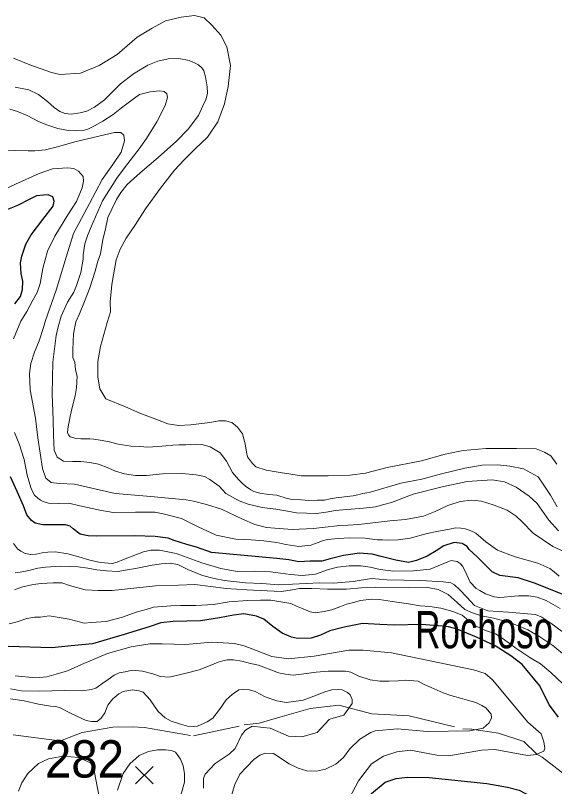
# Model space of a CAD drawing. Extents: x 474.5 to 500, y 7345.7 to 7373.4.
# Drawn here: x 485.568 to 486.724, y 7367.259 to 7368.914 of the extents above; entities that cross this region are included whole.
import ezdxf
from ezdxf.enums import TextEntityAlignment as Align

# ---------------------------------------------------------------- set-up
doc = ezdxf.new("R2010")
doc.units = 0
doc.header["$LTSCALE"] = 0.032
doc.linetypes.add('SHORT_DASHED', pattern=[2.7, 1.5, -1.2])
for name, color, linetype, lineweight in [('1', 7, 'Continuous', 25), ('16', 7, 'SHORT_DASHED', 13), ('2', 7, 'Continuous', 13), ('21', 7, 'Continuous', 25)]:
    doc.layers.add(name, color=color, linetype=linetype, lineweight=lineweight)
doc.layers.add('61', color=7, linetype='Continuous')

msp = doc.modelspace()

# ---------------------------------------------------------------- linework, layer by layer
at = {"layer": '1'}
for points in [[(485.5666, 7368.2952), (485.5789, 7368.3109), (485.583, 7368.3258), (485.5836, 7368.3436), (485.5802, 7368.3599), (485.5789, 7368.3831), (485.5816, 7368.3974), (485.5905, 7368.4226), (485.6014, 7368.4431), (485.6266, 7368.4758), (485.6491, 7368.5044), (485.6511, 7368.5153), (485.6484, 7368.5242), (485.6382, 7368.5289), (485.6279, 7368.5283), (485.6129, 7368.5269), (485.5973, 7368.5187), (485.5721, 7368.5058), (485.5325, 7368.4901)], [(486.225, 7367.7431), (486.1997, 7367.7431), (486.1752, 7367.7418), (486.1541, 7367.7459), (486.1282, 7367.7486), (485.9885, 7367.7615), (485.9564, 7367.7731), (485.9353, 7367.7786), (485.908, 7367.7874), (485.8951, 7367.7922), (485.8672, 7367.7956), (485.8242, 7367.797), (485.7411, 7367.7963), (485.724, 7367.797), (485.707, 7367.8011), (485.692, 7367.812), (485.6852, 7367.8181), (485.675, 7367.8208), (485.6634, 7367.8208), (485.6457, 7367.8208), (485.6266, 7367.8208), (485.6102, 7367.8242), (485.6021, 7367.8299), (485.5925, 7367.8426), (485.585, 7367.8617), (485.5714, 7367.8924), (485.5571, 7367.9237)], [(486.7402, 7367.6723), (486.6809, 7367.6954), (486.6455, 7367.707), (486.6066, 7367.7125), (486.5902, 7367.72), (486.5575, 7367.752), (486.5405, 7367.7677), (486.5364, 7367.7745), (486.5255, 7367.7806), (486.5085, 7367.7827), (486.486, 7367.7759), (486.4696, 7367.765), (486.4505, 7367.754), (486.4274, 7367.7445), (486.4103, 7367.7404), (486.3831, 7367.7452), (486.3517, 7367.7527), (486.3326, 7367.7581), (486.3047, 7367.7602), (486.2911, 7367.7581), (486.2713, 7367.7554), (486.2427, 7367.7479), (486.225, 7367.7431)], [(486.712, 7367.4346), (486.6924, 7367.4752), (486.6541, 7367.5213), (486.6298, 7367.5401), (486.5962, 7367.5612), (486.5563, 7367.58), (486.5148, 7367.5972), (486.496, 7367.6019), (486.4835, 7367.6035), (486.4374, 7367.6074), (486.3802, 7367.6058), (486.3489, 7367.6074), (486.3122, 7367.609), (486.273, 7367.6011), (486.2417, 7367.5933), (486.2222, 7367.5839), (486.2018, 7367.5777), (486.1729, 7367.5769), (486.1596, 7367.58), (486.14, 7367.5886), (486.1197, 7367.6027), (486.1001, 7367.6184), (486.0845, 7367.6246), (486.0578, 7367.6301), (486.0352, 7367.627), (486.0054, 7367.6215), (485.9647, 7367.6152), (485.906, 7367.6137), (485.8794, 7367.6105), (485.8544, 7367.6019), (485.8012, 7367.5855), (485.7331, 7367.5659), (485.6877, 7367.5612), (485.6463, 7367.5573), (485.5524, 7367.5597)], [(486.7321, 7367.4081), (486.712, 7367.4346)], [(486.2289, 7367.1554), (486.2404, 7367.1554), (486.2526, 7367.1591), (486.2725, 7367.1732), (486.3093, 7367.2226), (486.3313, 7367.2447), (486.3602, 7367.2686), (486.3841, 7367.2766), (486.4087, 7367.2798), (486.455, 7367.2791), (486.5783, 7367.2659), (486.6226, 7367.2584), (486.6476, 7367.2517), (486.6709, 7367.2393), (486.6958, 7367.2218), (486.7433, 7367.1823)]]:
    msp.add_lwpolyline(points, dxfattribs=at)
at = {"layer": '16'}
for points in [[(486.7287, 7367.9511), (486.7154, 7367.9692), (486.7022, 7367.9764), (486.6841, 7367.9836), (486.642, 7367.9848), (486.577, 7367.9848), (486.5276, 7367.98), (486.4891, 7367.9728), (486.4385, 7367.9584), (486.3651, 7367.9439), (486.3182, 7367.9319), (486.2845, 7367.9271), (486.2387, 7367.9259), (486.1809, 7367.9259), (486.1352, 7367.9331), (486.1051, 7367.9379), (486.0834, 7367.9451), (486.0762, 7367.9523), (486.0654, 7367.9668), (486.063, 7367.9764), (486.0606, 7367.9945), (486.0545, 7368.0161), (486.0437, 7368.0306), (486.0317, 7368.0402), (486.0184, 7368.0438), (486.004, 7368.0438), (485.9847, 7368.0402), (485.9438, 7368.0354), (485.9173, 7368.0342), (485.8944, 7368.0378), (485.8692, 7368.0474), (485.8343, 7368.0607), (485.8042, 7368.0739), (485.7616, 7368.091), (485.7488, 7368.1128), (485.7449, 7368.1373), (485.7449, 7368.1709), (485.75, 7368.2032), (485.7643, 7368.2549), (485.772, 7368.2781), (485.7707, 7368.3001), (485.7733, 7368.3207), (485.7746, 7368.3362), (485.7785, 7368.3569), (485.7836, 7368.3892), (485.7927, 7368.4124), (485.8056, 7368.4357), (485.825, 7368.4654), (485.8469, 7368.499), (485.8792, 7368.5429), (485.9089, 7368.5816), (485.9296, 7368.6036), (485.9541, 7368.6281), (485.98, 7368.6527), (486.0019, 7368.685), (486.0161, 7368.7237), (486.0239, 7368.7612), (486.029, 7368.8064), (486.0213, 7368.8464), (486.0084, 7368.871), (485.989, 7368.8929), (485.9722, 7368.9084), (485.9515, 7368.9136), (485.9231, 7368.9097), (485.8895, 7368.902), (485.8611, 7368.8865)], [(485.8611, 7368.8865), (485.8288, 7368.8671), (485.7862, 7368.8296), (485.7475, 7368.8064), (485.7074, 7368.7896), (485.6635, 7368.787), (485.6454, 7368.7909), (485.5989, 7368.8077), (485.5641, 7368.8219)], [(485.5634, 7367.3703), (485.6649, 7367.3573), (485.7113, 7367.3752), (485.7769, 7367.3869), (485.8183, 7367.3874), (485.8446, 7367.3864), (485.95, 7367.3681), (486.0583, 7367.3915), (486.0907, 7367.3952), (486.1348, 7367.4084), (486.2, 7367.4267), (486.261, 7367.4337), (486.3323, 7367.4156), (486.4123, 7367.4113), (486.5267, 7367.3832), (486.5461, 7367.3824), (486.5454, 7367.3825), (486.6034, 7367.374), (486.6575, 7367.3561), (486.6858, 7367.3286), (486.6974, 7367.3228), (486.7471, 7367.2839)]]:
    msp.add_lwpolyline(points, dxfattribs=at)
at = {"layer": '2'}
for points in [[(485.5674, 7368.7597), (485.5967, 7368.7537), (485.6172, 7368.7441), (485.6365, 7368.7286), (485.6507, 7368.7163), (485.663, 7368.7073), (485.6749, 7368.703), (485.6872, 7368.702), (485.7068, 7368.7046), (485.721, 7368.7083), (485.7372, 7368.7166), (485.7591, 7368.7325), (485.7931, 7368.7668), (485.8209, 7368.788), (485.8521, 7368.8072), (485.8733, 7368.8158), (485.8951, 7368.8208), (485.9181, 7368.821), (485.9405, 7368.8167), (485.953, 7368.8111), (485.9607, 7368.8077), (485.9673, 7368.8011), (485.9716, 7368.7945), (485.9756, 7368.7816), (485.9792, 7368.7607), (485.9794, 7368.7468), (485.9771, 7368.7348), (485.9698, 7368.7199), (485.9602, 7368.6987), (485.938, 7368.6696), (485.9135, 7368.644), (485.8739, 7368.6089), (485.8355, 7368.5761), (485.8078, 7368.5506), (485.7936, 7368.5337), (485.7843, 7368.5184), (485.7747, 7368.4982), (485.7663, 7368.4803), (485.7603, 7368.4521), (485.7553, 7368.4326), (485.7502, 7368.4024), (485.7449, 7368.3865), (485.7389, 7368.365), (485.7271, 7368.3295), (485.7159, 7368.2997), (485.7051, 7368.2732), (485.6975, 7368.2566), (485.6925, 7368.2308), (485.6907, 7368.1965), (485.6913, 7368.1799), (485.695, 7368.17), (485.6966, 7368.1531), (485.7003, 7368.1395), (485.699, 7368.115), (485.696, 7368.0978), (485.6882, 7368.0667), (485.6856, 7368.0534), (485.6836, 7368.0454), (485.6809, 7368.0319), (485.6794, 7368.0186), (485.6814, 7368.0137), (485.685, 7368.0097), (485.6907, 7368.008), (485.6973, 7368.0061), (485.7082, 7368.0051), (485.7274, 7368.0054), (485.7357, 7368.0047), (485.7496, 7368.0027), (485.7698, 7367.9988), (485.7884, 7367.9941), (485.816, 7367.9895), (485.8346, 7367.9888), (485.8521, 7367.9878), (485.873, 7367.9891), (485.8902, 7367.9905), (485.9055, 7367.9918), (485.919, 7367.9924), (485.9333, 7367.9928), (485.9439, 7367.9934)], [(486.1479, 7367.8511), (486.1259, 7367.8542), (486.0972, 7367.8581), (486.0672, 7367.8652), (486.0474, 7367.8722), (486.0188, 7367.8881), (486.0046, 7367.9035), (485.9844, 7367.9181), (485.9733, 7367.9242), (485.9553, 7367.9282), (485.9244, 7367.9313), (485.8834, 7367.93), (485.849, 7367.9269), (485.8252, 7367.9265), (485.8019, 7367.9304), (485.7825, 7367.9357), (485.7684, 7367.9423), (485.7463, 7367.9507), (485.7274, 7367.9547), (485.708, 7367.9564), (485.6903, 7367.9564), (485.6709, 7367.9573), (485.6577, 7367.9661), (485.6513, 7367.9809), (485.6498, 7368.0124), (485.6485, 7368.0459), (485.6467, 7368.1015), (485.648, 7368.1698), (485.6551, 7368.2267), (485.6595, 7368.2456), (485.6657, 7368.2685), (485.6798, 7368.2985), (485.693, 7368.3201), (485.6987, 7368.3342), (485.708, 7368.362), (485.7133, 7368.3906), (485.7133, 7368.4003), (485.7168, 7368.4233), (485.7234, 7368.4427), (485.7344, 7368.4704), (485.7547, 7368.5158), (485.7856, 7368.5643), (485.8036, 7368.5895), (485.8332, 7368.6274), (485.8486, 7368.6499), (485.8711, 7368.6851), (485.8892, 7368.7204), (485.894, 7368.7376), (485.8927, 7368.7455), (485.8865, 7368.7504), (485.8764, 7368.7517), (485.857, 7368.7499), (485.8336, 7368.7442), (485.8151, 7368.7305), (485.7953, 7368.7155), (485.7776, 7368.701), (485.7556, 7368.6869), (485.7375, 7368.6767), (485.7234, 7368.6693), (485.7128, 7368.6666), (485.6992, 7368.6657), (485.6815, 7368.667), (485.6586, 7368.671), (485.633, 7368.6794), (485.6172, 7368.6864), (485.5934, 7368.6992), (485.5722, 7368.7072), (485.5559, 7368.7125)], [(485.8018, 7368.6447), (485.8004, 7368.6564), (485.7937, 7368.6622), (485.7802, 7368.6622), (485.6981, 7368.6429), (485.6555, 7368.6308), (485.6326, 7368.6254), (485.6093, 7368.6232), (485.5953, 7368.6232), (485.5424, 7368.6245)], [(486.7842, 7367.7449), (486.72, 7367.7741), (486.6778, 7367.8033), (486.6545, 7367.8275), (486.6415, 7367.8396), (486.6222, 7367.8522), (486.5939, 7367.8629), (486.567, 7367.8715), (486.5463, 7367.8737), (486.5212, 7367.8706), (486.4947, 7367.8621), (486.4678, 7367.8495), (486.4426, 7367.8396), (486.4041, 7367.832), (486.3704, 7367.8297), (486.3044, 7367.8217), (486.2573, 7367.819), (486.207, 7367.8127), (486.1613, 7367.8109), (486.133, 7367.8127), (486.1065, 7367.8154), (486.0814, 7367.8217), (486.0545, 7367.8333), (486.01, 7367.8544), (485.9773, 7367.8643), (485.9499, 7367.8715), (485.9342, 7367.8746), (485.8583, 7367.8818), (485.7816, 7367.8881), (485.7286, 7367.9002), (485.6945, 7367.9083), (485.6622, 7367.9092), (485.6492, 7367.911), (485.6443, 7367.9119), (485.633, 7367.9208), (485.6259, 7367.9419), (485.616, 7368.0075), (485.6111, 7368.0496), (485.5998, 7368.1102), (485.598, 7368.1457), (485.6012, 7368.1668), (485.6088, 7368.191), (485.6187, 7368.2157), (485.6281, 7368.244), (485.6321, 7368.2592), (485.655, 7368.3243), (485.6766, 7368.3948), (485.6927, 7368.4459), (485.7264, 7368.5101), (485.7542, 7368.5613), (485.7767, 7368.5936), (485.7946, 7368.6205), (485.8018, 7368.6447)], [(485.5636, 7368.22), (485.5795, 7368.2577), (485.5922, 7368.2788), (485.6052, 7368.3029), (485.6142, 7368.3193), (485.6213, 7368.3383), (485.627, 7368.3705), (485.6369, 7368.408), (485.6522, 7368.4404), (485.6801, 7368.4862), (485.6991, 7368.5141), (485.7108, 7368.5439), (485.7142, 7368.5583), (485.7135, 7368.568), (485.7035, 7368.5797), (485.6928, 7368.5854), (485.6797, 7368.5867), (485.6476, 7368.5847), (485.6189, 7368.5744), (485.5684, 7368.5519), (485.5422, 7368.5392)], [(486.1475, 7367.7785), (486.1285, 7367.7829), (486.1007, 7367.7862), (486.0736, 7367.7886), (486.0404, 7367.7899), (485.9983, 7367.7986), (485.9595, 7367.8163), (485.9237, 7367.8347), (485.8843, 7367.8448), (485.8668, 7367.8481), (485.825, 7367.8477), (485.7775, 7367.8471), (485.7491, 7367.8521), (485.7059, 7367.8618), (485.6825, 7367.8671), (485.6598, 7367.8665), (485.6387, 7367.8675), (485.6276, 7367.8708), (485.6216, 7367.8738), (485.6159, 7367.8782), (485.6086, 7367.8845), (485.6049, 7367.8912), (485.6012, 7367.9013), (485.5929, 7367.9274), (485.5865, 7367.9612), (485.5758, 7367.9946), (485.5658, 7368.0187)], [(485.9439, 7367.9934), (485.9541, 7367.9938), (485.9675, 7367.9931), (485.9854, 7367.9882), (485.9927, 7367.9839), (486.0066, 7367.9756), (486.0205, 7367.9574), (486.0331, 7367.9328), (486.0459, 7367.9179), (486.0545, 7367.9093), (486.0614, 7367.9036), (486.0727, 7367.8957), (486.079, 7367.8927), (486.0919, 7367.8891), (486.1111, 7367.8861), (486.1283, 7367.8844), (486.1508, 7367.8775), (486.1615, 7367.8755), (486.1814, 7367.8745), (486.1966, 7367.8732), (486.2155, 7367.8735), (486.2307, 7367.8738), (486.2426, 7367.8765), (486.2552, 7367.8791), (486.2734, 7367.8808), (486.2923, 7367.8828), (486.3019, 7367.8851), (486.3119, 7367.8881), (486.3261, 7367.8904), (486.3942, 7367.9099), (486.4392, 7367.9186), (486.4814, 7367.9302), (486.5311, 7367.9424), (486.5688, 7367.9487), (486.602, 7367.9494), (486.6278, 7367.9464), (486.6568, 7367.9408), (486.6882, 7367.9239), (486.6995, 7367.908), (486.7151, 7367.8848), (486.7292, 7367.8593)], [(486.732, 7367.8083), (486.7117, 7367.8312), (486.6862, 7367.8665), (486.669, 7367.8824), (486.6416, 7367.9018), (486.6161, 7367.9132), (486.5901, 7367.9172), (486.5363, 7367.9137), (486.4825, 7367.9026), (486.4204, 7367.8863), (486.3741, 7367.8691), (486.3578, 7367.8643), (486.3401, 7367.8594), (486.3141, 7367.8564), (486.2696, 7367.8533), (486.2542, 7367.8515), (486.2343, 7367.848), (486.2136, 7367.8453), (486.192, 7367.8462), (486.1708, 7367.8467), (486.1479, 7367.8511)], [(486.7333, 7367.7107), (486.7232, 7367.7198), (486.7139, 7367.7271), (486.6875, 7367.7385), (486.639, 7367.7519), (486.6011, 7367.7665), (486.5763, 7367.7846), (486.5549, 7367.8027), (486.5429, 7367.8087), (486.5319, 7367.8124), (486.5225, 7367.8137), (486.5118, 7367.8141), (486.4984, 7367.8117), (486.4713, 7367.8067), (486.4506, 7367.802), (486.4143, 7367.792), (486.3886, 7367.7886), (486.3672, 7367.7879), (486.3548, 7367.7886), (486.3431, 7367.7889), (486.3174, 7367.7926), (486.2848, 7367.7933), (486.2601, 7367.7916), (486.2366, 7367.7893), (486.2263, 7367.7862), (486.2169, 7367.7829), (486.2012, 7367.7772), (486.1753, 7367.7745), (486.1475, 7367.7785)], [(486.0434, 7367.7206), (486.0082, 7367.727), (485.9675, 7367.7395), (485.9122, 7367.7592), (485.877, 7367.7665), (485.8582, 7367.7665), (485.8423, 7367.7626), (485.8183, 7367.7536), (485.7994, 7367.7463), (485.7861, 7367.7408), (485.775, 7367.7378), (485.7501, 7367.7399), (485.7278, 7367.7451), (485.7038, 7367.7523), (485.6802, 7367.7588), (485.6536, 7367.7626), (485.6377, 7367.7622), (485.6253, 7367.7605), (485.6124, 7367.7579), (485.6013, 7367.7571), (485.5888, 7367.7596), (485.5794, 7367.7644), (485.5725, 7367.7695), (485.564, 7367.7806)], [(486.736, 7367.6413), (486.7056, 7367.6589), (486.6867, 7367.6657), (486.6687, 7367.6683), (486.6464, 7367.6687), (486.6292, 7367.6674), (486.6155, 7367.6657), (486.6056, 7367.6653), (486.5945, 7367.6666), (486.576, 7367.673), (486.5636, 7367.6799), (486.5559, 7367.6842), (486.5426, 7367.6979), (486.5353, 7367.7137), (486.5267, 7367.7318), (486.5211, 7367.7378), (486.5147, 7367.7421), (486.5019, 7367.7442), (486.4864, 7367.7382), (486.4744, 7367.7326), (486.4568, 7367.7258), (486.4212, 7367.7219), (486.3783, 7367.7215), (486.3496, 7367.7253), (486.3282, 7367.73), (486.3084, 7367.7326), (486.2836, 7367.7326), (486.2587, 7367.73), (486.239, 7367.7249), (486.2111, 7367.715), (486.1824, 7367.7125), (486.1579, 7367.7146), (486.1146, 7367.7198), (486.0799, 7367.7215), (486.0434, 7367.7206)], [(485.7234, 7367.7282), (485.7022, 7367.7309), (485.6654, 7367.7322), (485.6327, 7367.7302), (485.6157, 7367.7282), (485.5966, 7367.7227), (485.5782, 7367.7193), (485.5673, 7367.7179)], [(486.7402, 7367.5918), (486.7156, 7367.6102), (486.6966, 7367.6225), (486.6829, 7367.6286), (486.657, 7367.6307), (486.625, 7367.6334), (486.5807, 7367.6361), (486.5521, 7367.6477), (486.5357, 7367.6655), (486.5201, 7367.6825), (486.5091, 7367.692), (486.501, 7367.6961), (486.4846, 7367.6988), (486.4369, 7367.7016), (486.364, 7367.7029), (486.3313, 7367.7057), (486.2917, 7367.6995), (486.2495, 7367.6954), (486.2202, 7367.6961), (486.1329, 7367.692), (486.0961, 7367.6948), (486.0614, 7367.6968), (486.0164, 7367.7016), (485.9939, 7367.7057), (485.9687, 7367.7125), (485.9374, 7367.7247), (485.9162, 7367.7356), (485.8999, 7367.7384), (485.8808, 7367.737), (485.861, 7367.7343), (485.8256, 7367.7275), (485.8072, 7367.7241), (485.7881, 7367.7207), (485.7629, 7367.722), (485.7424, 7367.7241), (485.7234, 7367.7282)], [(486.749, 7367.538), (486.7197, 7367.5619), (486.6918, 7367.5803), (486.6666, 7367.5959), (486.6284, 7367.6116), (486.593, 7367.6205), (486.5671, 7367.6259), (486.548, 7367.6321), (486.531, 7367.6396), (486.5146, 7367.6545), (486.4955, 7367.6716), (486.4744, 7367.6818), (486.4519, 7367.6866), (486.4124, 7367.6859), (486.3388, 7367.6873), (486.3095, 7367.6859), (486.2774, 7367.6832), (486.2372, 7367.6832), (486.2031, 7367.6845), (486.1766, 7367.6845), (486.1616, 7367.6811), (486.1377, 7367.6777), (486.1077, 7367.6791), (486.0641, 7367.6811), (486.0198, 7367.6845), (485.9523, 7367.6927), (485.9176, 7367.6913), (485.8685, 7367.69), (485.8283, 7367.6859), (485.7956, 7367.6818), (485.7751, 7367.6798), (485.7452, 7367.6798), (485.7172, 7367.6811), (485.6838, 7367.6907), (485.6675, 7367.6961), (485.6491, 7367.6961), (485.6232, 7367.6948), (485.6061, 7367.6927), (485.5809, 7367.6873), (485.5659, 7367.6811)], [(486.7417, 7367.4799), (486.7159, 7367.5041), (486.6932, 7367.5229), (486.6705, 7367.5362), (486.6408, 7367.5565), (486.6134, 7367.5761), (486.597, 7367.5871), (486.5759, 7367.5941), (486.5539, 7367.6043), (486.5391, 7367.616), (486.5258, 7367.627), (486.5054, 7367.6348), (486.4796, 7367.6418), (486.4561, 7367.6457), (486.4358, 7367.6473), (486.4107, 7367.6512), (486.3755, 7367.6567), (486.3474, 7367.6606), (486.3317, 7367.6614), (486.3067, 7367.6583), (486.2957, 7367.6551), (486.2777, 7367.6504), (486.2636, 7367.645), (486.2464, 7367.6387), (486.23, 7367.6348), (486.2104, 7367.6324), (486.1995, 7367.634), (486.1815, 7367.6418), (486.1705, 7367.6465), (486.158, 7367.652), (486.1158, 7367.6591), (486.0931, 7367.6591), (486.0657, 7367.6583), (486.0258, 7367.6559), (485.9929, 7367.6497), (485.9546, 7367.6481), (485.9217, 7367.6481), (485.9013, 7367.6473), (485.8638, 7367.6442), (485.8481, 7367.6395), (485.827, 7367.6332), (485.7973, 7367.6231), (485.7628, 7367.6137), (485.73, 7367.6113), (485.7151, 7367.6098), (485.683, 7367.6184), (485.6658, 7367.6215), (485.64, 7367.6254), (485.622, 7367.6231), (485.6087, 7367.6231), (485.5923, 7367.6199), (485.5719, 7367.6129), (485.5547, 7367.6082)], [(486.2756, 7367.2185), (486.3033, 7367.2716), (486.3316, 7367.3079), (486.3567, 7367.3243), (486.3859, 7367.3341), (486.4146, 7367.3372), (486.4713, 7367.3269), (486.4966, 7367.3253), (486.5678, 7367.3373), (486.5955, 7367.3389), (486.6659, 7367.3261), (486.6851, 7367.3283), (486.6858, 7367.3286), (486.701, 7367.3357), (486.7029, 7367.3419), (486.7006, 7367.3555), (486.6947, 7367.3728), (486.6665, 7367.3979), (486.5907, 7367.4885), (486.5751, 7367.5018), (486.55, 7367.5099), (486.3739, 7367.5465), (486.3134, 7367.5522), (486.2826, 7367.5522), (486.2082, 7367.5392), (486.1533, 7367.5332), (486.1179, 7367.5384), (486.0584, 7367.5615), (486.0373, 7367.566), (485.9889, 7367.569), (485.9327, 7367.5642), (485.8825, 7367.5655), (485.8564, 7367.5657), (485.8164, 7367.5594), (485.7652, 7367.5448), (485.7096, 7367.5213), (485.6799, 7367.508), (485.6556, 7367.5002), (485.6353, 7367.4947), (485.611, 7367.4924), (485.5672, 7367.4971)], [(486.5373, 7367.445), (486.5219, 7367.4493), (486.5015, 7367.4548), (486.4851, 7367.4603), (486.4593, 7367.472), (486.4444, 7367.4783), (486.4311, 7367.4853), (486.4037, 7367.4877), (486.3881, 7367.4861), (486.3685, 7367.4853), (486.3489, 7367.4853), (486.3286, 7367.4885), (486.3043, 7367.4963), (486.2871, 7367.5049), (486.2754, 7367.5072), (486.2605, 7367.5072), (486.2386, 7367.5072), (486.2128, 7367.5049), (486.1815, 7367.5002), (486.1635, 7367.4986), (486.1471, 7367.5002), (486.1322, 7367.5033), (486.1158, 7367.5096), (486.1001, 7367.5159), (486.0891, 7367.5198), (486.0719, 7367.5237), (486.0532, 7367.5284), (486.0352, 7367.5315), (486.0219, 7367.5315), (486.0125, 7367.5292), (486.0023, 7367.526), (485.9851, 7367.519), (485.9616, 7367.5096), (485.9366, 7367.5033), (485.9162, 7367.4986), (485.8974, 7367.4939), (485.8787, 7367.4955), (485.8622, 7367.501), (485.8403, 7367.5072), (485.8192, 7367.5088), (485.8035, 7367.5057), (485.7902, 7367.5033), (485.7793, 7367.4986), (485.7668, 7367.4893), (485.755, 7367.4814), (485.7402, 7367.4705), (485.7308, 7367.4673), (485.7104, 7367.465), (485.6736, 7367.4658), (485.6181, 7367.4642), (485.5813, 7367.465), (485.5571, 7367.4689)], [(485.9711, 7367.2562), (485.971, 7367.277), (485.9748, 7367.2861), (485.9958, 7367.3087), (486.026, 7367.3286), (486.0392, 7367.3411), (486.0523, 7367.3695), (486.0605, 7367.38), (486.0636, 7367.3819), (486.0752, 7367.3889), (486.0989, 7367.3862), (486.1142, 7367.3844), (486.153, 7367.3675), (486.182, 7367.366), (486.2145, 7367.3752), (486.2405, 7367.4034), (486.2439, 7367.4044), (486.2719, 7367.4129), (486.29, 7367.4373), (486.2899, 7367.4463), (486.2852, 7367.4559), (486.2796, 7367.461), (486.2683, 7367.4666), (486.2613, 7367.4673), (486.2464, 7367.4666), (486.2331, 7367.4634), (486.2073, 7367.4533), (486.1846, 7367.4446), (486.1494, 7367.44), (486.1283, 7367.4431), (486.1032, 7367.4517), (486.0821, 7367.4634), (486.0696, 7367.4666), (486.0563, 7367.4673), (486.0469, 7367.4666), (486.0373, 7367.4605), (486.0328, 7367.4572), (486.0196, 7367.4456), (486.0055, 7367.4246), (485.9913, 7367.4063), (485.9788, 7367.3985), (485.9585, 7367.3891), (485.9491, 7367.3883), (485.9366, 7367.3891), (485.9217, 7367.393), (485.9021, 7367.4), (485.8888, 7367.4071), (485.874, 7367.4204), (485.8567, 7367.4454), (485.8419, 7367.4619), (485.8333, 7367.465), (485.8184, 7367.4666), (485.7988, 7367.4634), (485.7895, 7367.458), (485.7769, 7367.4478), (485.766, 7367.4337), (485.7595, 7367.4174), (485.7519, 7367.4063), (485.7433, 7367.3993), (485.7308, 7367.3993), (485.7198, 7367.4008), (485.7026, 7367.4087), (485.683, 7367.418), (485.6635, 7367.4282), (485.6549, 7367.4313), (485.6431, 7367.4321), (485.6173, 7367.436), (485.5868, 7367.4431), (485.5571, 7367.4478)], [(486.025, 7367.2185), (486.0385, 7367.2636), (486.0488, 7367.2859), (486.0788, 7367.3177), (486.0921, 7367.3268), (486.1035, 7367.3308), (486.1215, 7367.33), (486.1545, 7367.3084), (486.1737, 7367.2988), (486.1928, 7367.2933), (486.2134, 7367.2927), (486.233, 7367.297), (486.2546, 7367.3076), (486.2713, 7367.3218), (486.2851, 7367.3404), (486.3064, 7367.3609), (486.3296, 7367.3754), (486.3393, 7367.3787), (486.3872, 7367.3835), (486.4509, 7367.3772), (486.5417, 7367.3787), (486.5418, 7367.3787), (486.5703, 7367.3845), (486.5836, 7367.3959), (486.5882, 7367.4069), (486.5879, 7367.4149), (486.5767, 7367.4284), (486.5681, 7367.433), (486.5552, 7367.4401), (486.5373, 7367.445)], [(485.7864, 7367.2519), (485.7988, 7367.2874), (485.8134, 7367.3083), (485.833, 7367.3259), (485.8535, 7367.3349), (485.8728, 7367.3383), (485.8899, 7367.3383), (485.9027, 7367.3366), (485.9108, 7367.3331), (485.922, 7367.3182), (485.9275, 7367.3041), (485.9305, 7367.2878), (485.9301, 7367.269), (485.9228, 7367.2412)], [(485.5743, 7367.2496), (485.5818, 7367.2676), (485.5947, 7367.2878), (485.6172, 7367.3086), (485.6391, 7367.3189), (485.6701, 7367.3244), (485.7028, 7367.3218), (485.7288, 7367.3106), (485.7367, 7367.293), (485.7523, 7367.2113)]]:
    msp.add_lwpolyline(points, dxfattribs=at)
at = {"layer": '21'}
for p, q in [((485.8256, 7367.3028), (485.8631, 7367.2653)), ((485.8631, 7367.3028), (485.8256, 7367.2653))]:
    msp.add_line(p, q, dxfattribs=at)

# ---------------------------------------------------------------- texts
at = {"layer": '61', "width": 0.7}
msp.add_text('Rochoso', height=0.08, dxfattribs=at).set_placement((486.425, 7367.5561))
at = {"layer": '61', "width": 0.95}
msp.add_text('282', height=0.08, dxfattribs=at).set_placement((485.716, 7367.2788), align=Align.CENTER)

doc.saveas('drawing.dxf')
